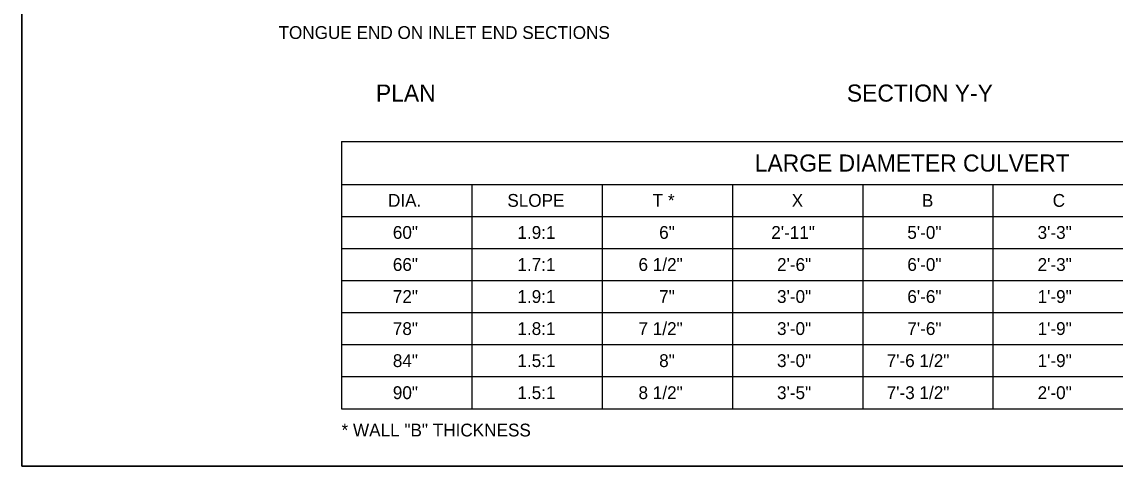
# Model space of a CAD drawing. Extents: x 49991.4 to 50021, y 49987.6 to 50011.4.
# Drawn here: x 49999.38 to 50004.5, y 49987.8 to 49989.88 of the extents above; entities that cross this region are included whole.
import ezdxf

# ---------------------------------------------------------------- set-up
doc = ezdxf.new("R2010")
doc.units = 0
doc.layers.add('Level 1', color=7, linetype='Continuous')
doc.layers.add('Level 2', color=7, linetype='Continuous')

msp = doc.modelspace()

# ---------------------------------------------------------------- linework, layer by layer
at = {"layer": 'Level 1'}
msp.add_lwpolyline([(49999.3835, 49998.9992), (50016.7501, 49998.9992), (50016.7501, 49987.7988), (49999.3835, 49987.7988)], close=True, dxfattribs=at)
at = {"layer": 'Level 2'}
for p, q in [((49999.3835, 49998.9992), (49999.3835, 49987.7988)), ((50000.8802, 49989.3176), (50000.8802, 49988.0676)), ((50000.8802, 49989.3176), (50006.3702, 49989.3176)), ((50000.8802, 49989.1176), (50000.8802, 49988.9676)), ((50000.8802, 49989.1176), (50006.3702, 49989.1176)), ((50001.4902, 49989.1176), (50001.4902, 49988.0676)), ((50002.1002, 49989.1176), (50002.1002, 49988.0676)), ((50002.7102, 49989.1176), (50002.7102, 49988.0676)), ((50003.3202, 49989.1176), (50003.3202, 49988.0676)), ((50003.9302, 49989.1176), (50003.9302, 49988.0676)), ((50000.8802, 49988.9676), (50006.3702, 49988.9676)), ((50000.8802, 49988.8176), (50006.3702, 49988.8176)), ((50000.8802, 49988.6676), (50006.3702, 49988.6676)), ((50000.8802, 49988.5176), (50006.3702, 49988.5176)), ((50000.8802, 49988.3676), (50006.3702, 49988.3676)), ((50000.8802, 49988.2176), (50006.3702, 49988.2176)), ((50000.8802, 49988.0676), (50006.3702, 49988.0676)), ((49999.3835, 49987.7988), (50016.7501, 49987.7988))]:
    msp.add_line(p, q, dxfattribs=at)

# ---------------------------------------------------------------- texts
for s, height, p in [('TONGUE END ON INLET END SECTIONS', 0.06, (50000.585, 49989.7983)), ('PLAN', 0.08, (50001.0412, 49989.505)), ('SECTION Y-Y', 0.08, (50003.2462, 49989.505)), ('LARGE DIAMETER CULVERT', 0.08, (50002.8149, 49989.1776)), ('DIA.', 0.06, (50001.0977, 49989.0126)), ('SLOPE', 0.06, (50001.6564, 49989.0126)), ('T *', 0.06, (50002.337, 49989.0126)), ('X', 0.06, (50002.9878, 49989.0126)), ('B', 0.06, (50003.5975, 49989.0126)), ('C', 0.06, (50004.2097, 49989.0126)), ('60"', 0.06, (50001.1203, 49988.8626)), ('1.9:1', 0.06, (50001.7036, 49988.8626)), ('6"', 0.06, (50002.3672, 49988.8626)), ('2\'-11"', 0.06, (50002.8922, 49988.8626)), ('5\'-0"', 0.06, (50003.5291, 49988.8626)), ('3\'-3"', 0.06, (50004.1391, 49988.8626)), ('66"', 0.06, (50001.1203, 49988.7126)), ('1.7:1', 0.06, (50001.7036, 49988.7126)), ('6 1/2"', 0.06, (50002.2705, 49988.7126)), ('2\'-6"', 0.06, (50002.9191, 49988.7126)), ('6\'-0"', 0.06, (50003.5291, 49988.7126)), ('2\'-3"', 0.06, (50004.1391, 49988.7126)), ('72"', 0.06, (50001.1203, 49988.5626)), ('1.9:1', 0.06, (50001.7036, 49988.5626)), ('7"', 0.06, (50002.3672, 49988.5626)), ('3\'-0"', 0.06, (50002.9191, 49988.5626)), ('6\'-6"', 0.06, (50003.5291, 49988.5626)), ('1\'-9"', 0.06, (50004.1391, 49988.5626)), ('78"', 0.06, (50001.1203, 49988.4126)), ('1.8:1', 0.06, (50001.7036, 49988.4126)), ('7 1/2"', 0.06, (50002.2705, 49988.4126)), ('3\'-0"', 0.06, (50002.9191, 49988.4126)), ('7\'-6"', 0.06, (50003.5291, 49988.4126)), ('1\'-9"', 0.06, (50004.1391, 49988.4126)), ('84"', 0.06, (50001.1203, 49988.2626)), ('1.5:1', 0.06, (50001.7036, 49988.2626)), ('8"', 0.06, (50002.3672, 49988.2626)), ('3\'-0"', 0.06, (50002.9191, 49988.2626)), ('7\'-6 1/2"', 0.06, (50003.4324, 49988.2626)), ('1\'-9"', 0.06, (50004.1391, 49988.2626)), ('90"', 0.06, (50001.1203, 49988.1126)), ('1.5:1', 0.06, (50001.7036, 49988.1126)), ('8 1/2"', 0.06, (50002.2705, 49988.1126)), ('3\'-5"', 0.06, (50002.9191, 49988.1126)), ('7\'-3 1/2"', 0.06, (50003.4324, 49988.1126)), ('2\'-0"', 0.06, (50004.1391, 49988.1126)), ('* WALL "B" THICKNESS', 0.06, (50000.8802, 49987.9376))]:
    msp.add_text(s, height=height, dxfattribs=at).set_placement(p)

doc.saveas('drawing.dxf')
